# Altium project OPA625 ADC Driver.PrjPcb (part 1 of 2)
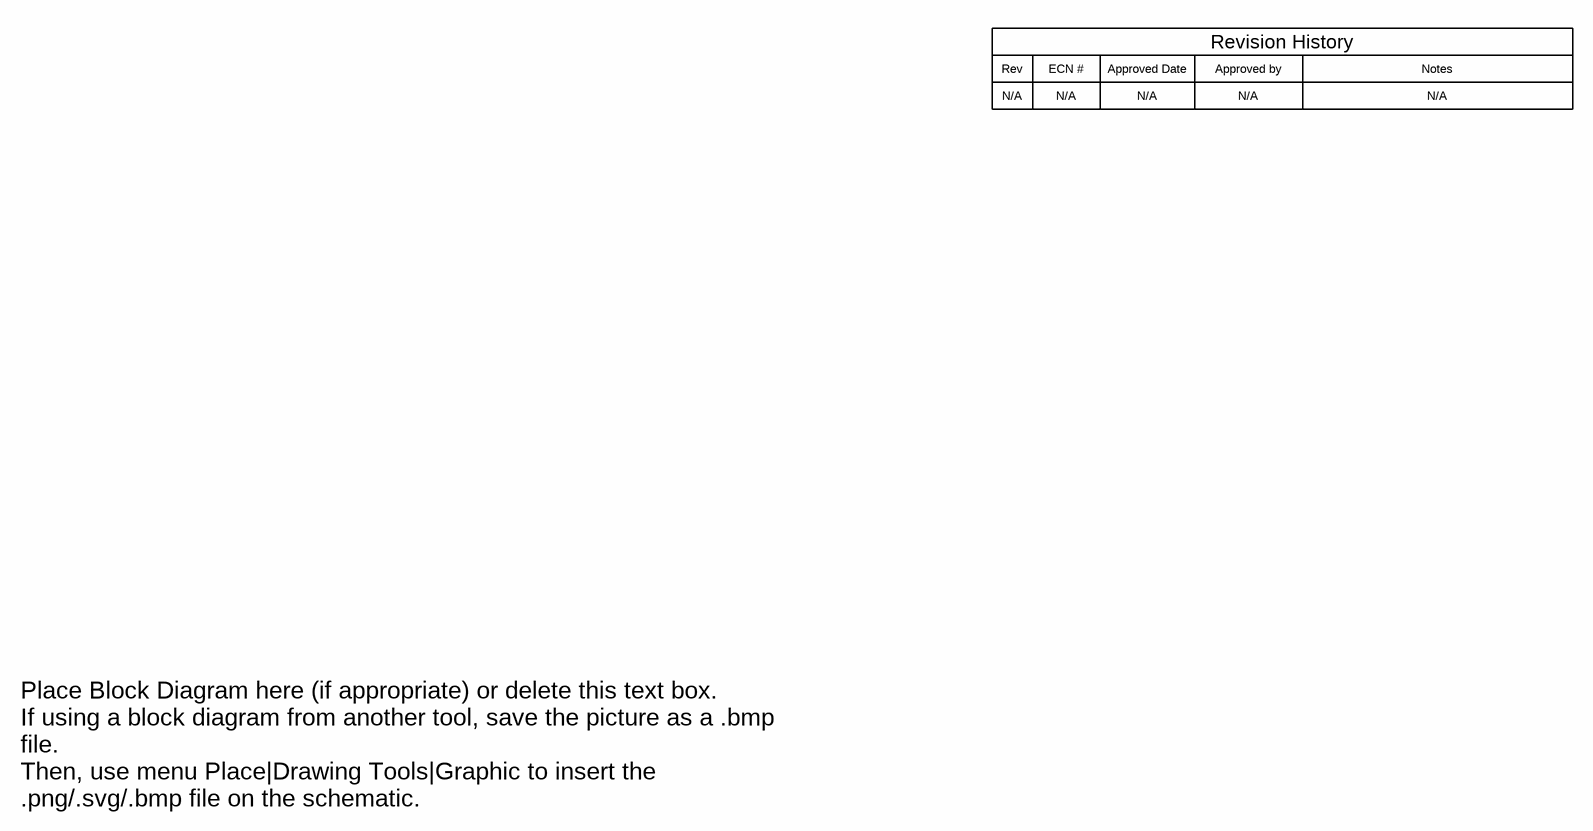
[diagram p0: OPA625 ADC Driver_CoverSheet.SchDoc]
CopyrightYear: 2016; EVM_Orderable: N/A; PCB_Rev: E1; PRJ_Customer: Public Release; PRJ_Engineer: Taras Dudar; PRJ_Number: TIDA-01050; PRJ_Title: OPA625 ADC Driver; SCH_Rev: E1; TechSupport: http://www.ti.com/support; TID: 01050
6 sheets, 429 parts. Net scope: global (net labels, ports and power ports of the same name join across sheets).
Board file: OPA625 ADC Driver.PcbDoc
Sheets:
  OPA625 ADC Driver_CoverSheet.SchDoc
  OPA625 ADC Driver_Power.SchDoc
  OPA625 ADC Driver_Connectors.SchDoc
  OPA625 ADC Driver_OPA625 ADC Driver.SchDoc
  OPA625 ADC Driver_Clock.SchDoc
  OPA625 ADC Driver_Hardware.SchDoc

## Sheet OPA625 ADC Driver_CoverSheet.SchDoc
size 431 x 279 mm; Date: Not shown in title block; ApprovedBy: Not shown in title block; CheckedBy: Not shown in title block; Author: Not shown in title block; CompanyName: Not shown in title block; Engineer: Not shown in title block; Organization: Not shown in title block; Address1: Not shown in title block; Address2: Not shown in title block; Address3: Not shown in title block; Address4: Not shown in title block; DocumentNumber: 1; Revision: Use project parameter SCH_Rev; SheetNumber: 1; SheetTotal: 8; PageSetup: Record=PageOptions¦CenterHorizontal=True¦CenterVertical=True¦PrintScale=1.00¦XCorrection=1.00¦YCorrection=1.00¦PrintKind=0¦BorderSize=5000000¦LeftOffset=0¦BottomOffset=0¦Orientation=2¦PaperLength=1000¦PaperWidth=1000¦Scale=100¦PaperSource=15¦PrintQuality=600¦MediaType=1¦DitherType=10¦PaperKind=Letter¦PrintScaleMode=1

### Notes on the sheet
- Rev
- N/A
- ECN #
- Approved Date
- Approved by
- Revision History
- Notes
- Place Block Diagram here (if appropriate) or delete this text box.
  If using a block diagram from another tool, save the picture as a .bmp file.
  Then, use menu Place|Drawing Tools|Graphic to insert the .png/.svg/.bmp file on the schematic.

## Sheet OPA625 ADC Driver_Power.SchDoc
size 558 x 431 mm; Date: Not shown in title block; ApprovedBy: Not shown in title block; CheckedBy: Not shown in title block; Author: Not shown in title block; CompanyName: Not shown in title block; Engineer: Not shown in title block; Organization: Not shown in title block; Address1: Not shown in title block; Address2: Not shown in title block; Address3: Not shown in title block; Address4: Not shown in title block; DocumentNumber: 2; Revision: Use project parameter SCH_Rev; SheetNumber: 2; SheetTotal: 8; PageSetup: Record=PageOptions¦CenterHorizontal=True¦CenterVertical=True¦PrintScale=1.00¦XCorrection=1.00¦YCorrection=1.00¦PrintKind=0¦BorderSize=5000000¦LeftOffset=0¦BottomOffset=0¦Orientation=2¦PaperLength=1000¦PaperWidth=1000¦Scale=100¦PaperSource=15¦PrintQuality=600¦MediaType=1¦DitherType=10¦PaperKind=Letter¦PrintScaleMode=1
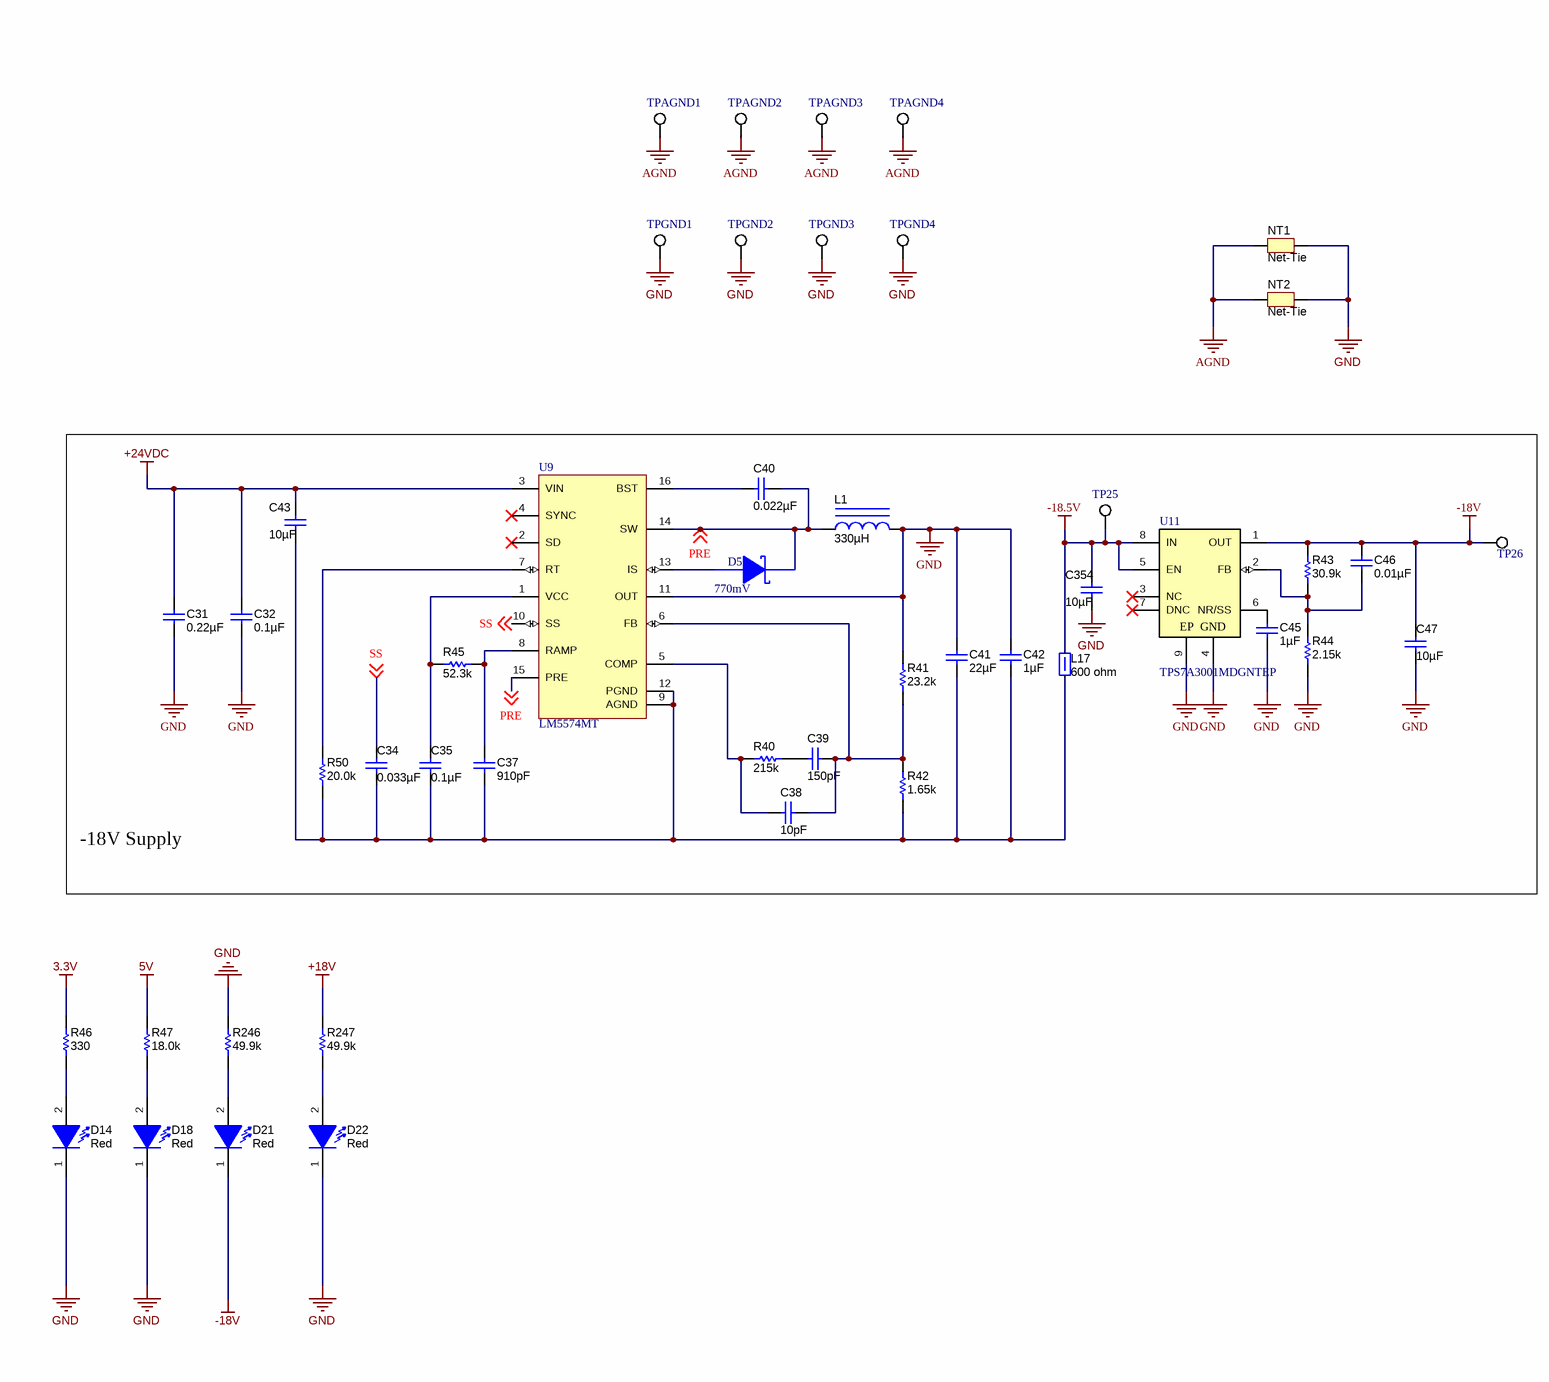
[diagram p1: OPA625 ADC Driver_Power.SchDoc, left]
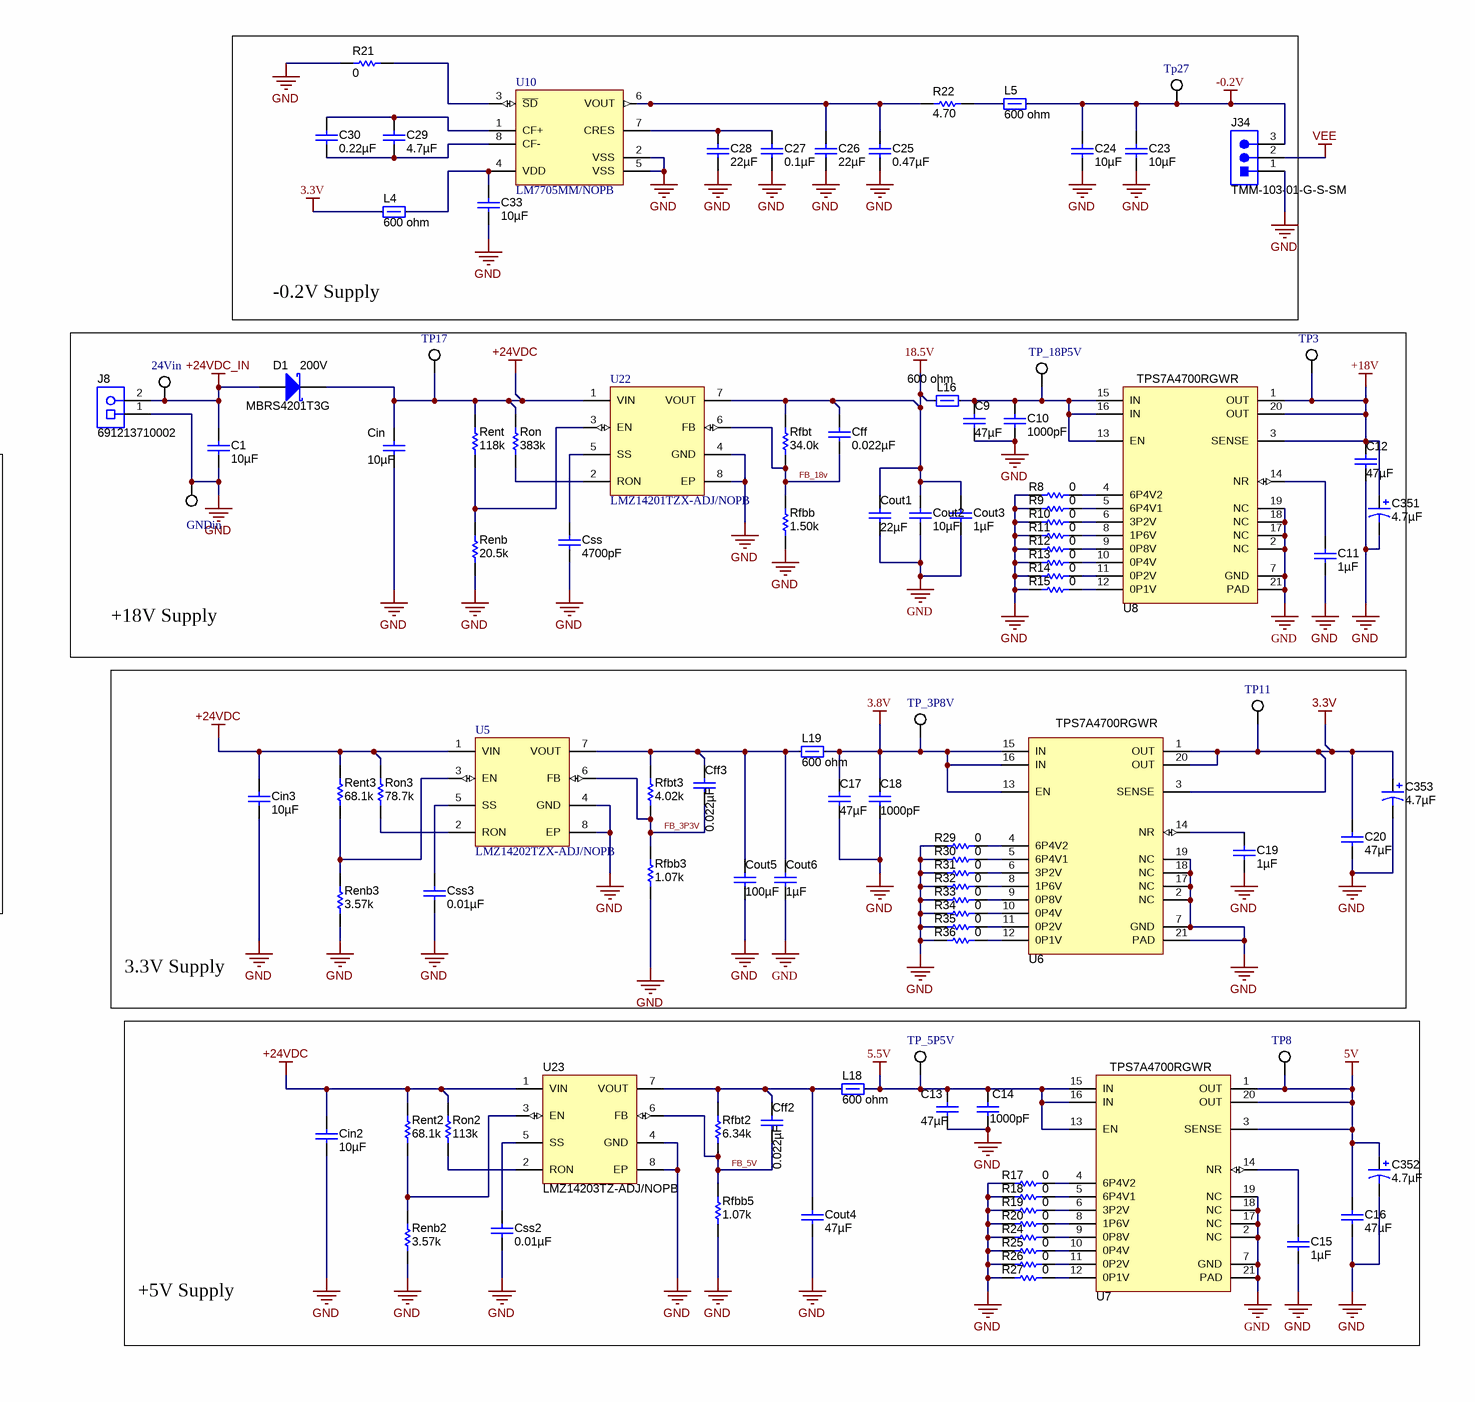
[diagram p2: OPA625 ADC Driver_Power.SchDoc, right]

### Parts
24Vin  5015  [Testpoint_Keystone_Miniature]  (value not drawn)
C1  ValueDisplayed: 10µF  [1210_280]  (hidden comment: UMK325AB7106KM-T)
C9  ValueDisplayed: 47µF  [1206_190]  (hidden comment: C3216X5R1E476M160AC)
C10  ValueDisplayed: 1000pF  [0603]  (hidden comment: CGA3E2X7R2A102K080AA)
C11  ValueDisplayed: 1µF  [0805_HV]  (hidden comment: C2012X7S2A105K125AB)
C12  ValueDisplayed: 47µF  [1206_190]  (hidden comment: C3216X5R1E476M160AC)
C13  ValueDisplayed: 47µF  [1206_190]  (hidden comment: C3216X5R1E476M160AC)
C14  ValueDisplayed: 1000pF  [0603]  (hidden comment: GRM1885C1H102FA01J)
C15  ValueDisplayed: 1µF  [0603]  (hidden comment: GRM188R71E105KA12D)
C16  ValueDisplayed: 47µF  [1206_190]  (hidden comment: C3216X5R1E476M160AC)
C17  ValueDisplayed: 47µF  [1206_190]  (hidden comment: C3216X5R1E476M160AC)
C18  ValueDisplayed: 1000pF  [0603]  (hidden comment: GRM1885C1H102FA01J)
C19  ValueDisplayed: 1µF  [0603]  (hidden comment: GRM188R71E105KA12D)
C20  ValueDisplayed: 47µF  [1206_190]  (hidden comment: C3216X5R1E476M160AC)
C23  ValueDisplayed: 10µF  [0603]  (hidden comment: GRM188R61A106ME69D)
C24  ValueDisplayed: 10µF  [0603]  (hidden comment: GRM188R61A106ME69D)
C25  ValueDisplayed: 0.47µF  [0603]  (hidden comment: GRM188R71E474KA12D)
C26  ValueDisplayed: 22µF  [0603]  (hidden comment: GRM188R60J226MEA0D)
C27  ValueDisplayed: 0.1µF  [0603]  (hidden comment: GRM188R61C104KA01D)
C28  ValueDisplayed: 22µF  [0603]  (hidden comment: GRM188R60J226MEA0D)
C29  ValueDisplayed: 4.7µF  [0603]  (hidden comment: GRM188R61A475MAAJ)
C30  ValueDisplayed: 0.22µF  [0603]  (hidden comment: GRM188R61A224KA01D)
C31  ValueDisplayed: 0.22µF  [0603]  (hidden comment: GCM188R71H224KA64D)
C32  ValueDisplayed: 0.1µF  [0603]  (hidden comment: C1608X7R1H104K080AA)
C33  ValueDisplayed: 10µF  [0603]  (hidden comment: GRM188R61A106ME69D)
C34  ValueDisplayed: 0.033µF  [0603]  (hidden comment: GRM188R71H333KA61D)
C35  ValueDisplayed: 0.1µF  [0603]  (hidden comment: C1608X7R1H104K080AA)
C37  ValueDisplayed: 910pF  [0603]  (hidden comment: C0603C911J5GACTU)
C38  ValueDisplayed: 10pF  [0603]  (hidden comment: CGA3E2C0G1H100D080AA)
C39  ValueDisplayed: 150pF  [0603]  (hidden comment: GRM1885C1H151JA01D)
C40  ValueDisplayed: 0.022µF  [0603]  (hidden comment: GRM188R71H223KA01D)
C41  ValueDisplayed: 22µF  [0805_HV]  (hidden comment: C2012X5R1V226M125AC)
C42  ValueDisplayed: 1µF  [0805_HV]  (hidden comment: C2012X7S2A105K125AB)
C43  ValueDisplayed: 10µF  [1210_280]  (hidden comment: UMK325AB7106KM-T)
C45  ValueDisplayed: 1µF  [0805_HV]  (hidden comment: C2012X7S2A105K125AB)
C46  ValueDisplayed: 0.01µF  [0603]  (hidden comment: GCM188R71H103KA37D)
C47  ValueDisplayed: 10µF  [1210_280]  (hidden comment: UMK325AB7106KM-T)
C351  ValueDisplayed: 4.7µF  [6032-28]  (hidden comment: 293D475X9025C2TE3)
C352  ValueDisplayed: 4.7µF  [6032-28]  (hidden comment: 293D475X9025C2TE3)
C353  ValueDisplayed: 4.7µF  [6032-28]  (hidden comment: 293D475X9025C2TE3)
C354  ValueDisplayed: 10µF  [1210_280]  (hidden comment: UMK325AB7106KM-T)
Cff  ValueDisplayed: 0.022µF  [0603]  (hidden comment: C1608X7R2A223K080AA)
Cff2  ValueDisplayed: 0.022µF  [0805_HV]  (hidden comment: 08055C223KAT2A)
Cff3  ValueDisplayed: 0.022µF  [0805_HV]  (hidden comment: 08055C223KAT2A)
Cin  ValueDisplayed: 10µF  [1210_280]  (hidden comment: UMK325AB7106KM-T)
Cin2  ValueDisplayed: 10µF  [1210_280]  (hidden comment: UMK325AB7106KM-T)
Cin3  ValueDisplayed: 10µF  [1210_280]  (hidden comment: UMK325AB7106KM-T)
Cout1  ValueDisplayed: 22µF  [0805_HV]  (hidden comment: C2012JB1V226M125AC)
Cout2  ValueDisplayed: 10µF  [1210_280]  (hidden comment: UMK325AB7106KM-T)
Cout3  ValueDisplayed: 1µF  [0805_HV]  (hidden comment: C2012X7S2A105K125AB)
Cout4  ValueDisplayed: 47µF  [1206_190]  (hidden comment: C3216X5R1E476M160AC)
Cout5  ValueDisplayed: 100µF  [1210_280]  (hidden comment: C3225X6S0J107M250AC)
Cout6  ValueDisplayed: 1µF  [0603]  (hidden comment: C0603C105K3RACTU)
Css  ValueDisplayed: 4700pF  [0603]  (hidden comment: CGA3E2X7R2A472K080AA)
Css2  ValueDisplayed: 0.01µF  [0603]  (hidden comment: GRM188R70J103KA01D)
Css3  ValueDisplayed: 0.01µF  [0603]  (hidden comment: GRM188R70J103KA01D)
D1  value 200V  [SMC]  (hidden comment: MBRS4201T3G)
D5  value 770mV  (hidden comment: DFLS1100-7)
D14  value Red  [WL-SMCW_RED]  (hidden comment: 150060RS75000)
D18  value Red  [WL-SMCW_RED]  (hidden comment: 150060RS75000)
D21  value Red  [WL-SMCW_RED]  (hidden comment: 150060RS75000)
D22  value Red  [WL-SMCW_RED]  (hidden comment: 150060RS75000)
GNDin  5015  [Testpoint_Keystone_Miniature]  (value not drawn)
J8  691213710002  [Wurth_691213710002]
J34  TMM-103-01-G-S-SM  [Samtec_TMM-103-01-x-S-SM]
L1  ValueDisplayed: 330µH  [DR73]  (hidden comment: DR73-331-R)
L4  value 600 ohm  [0805_HV]  (hidden comment: MPZ2012S601A)
L5  value 600 ohm  [0805_HV]  (hidden comment: MPZ2012S601A)
L16  value 600 ohm  [0805_HV]  (hidden comment: MPZ2012S601A)
L17  value 600 ohm  [0805_HV]  (hidden comment: MPZ2012S601A)
L18  value 600 ohm  [0805_HV]  (hidden comment: MPZ2012S601A)
L19  value 600 ohm  [0805_HV]  (hidden comment: MPZ2012S601A)
NT1  Net-Tie  [Net-Tie_50milWide_30milLong]  (net tie, no BOM)
NT2  Net-Tie  [Net-Tie_50milWide_30milLong]  (net tie, no BOM)
R8  ValueDisplayed: 0  [0402]  (hidden comment: ERJ-2GE0R00X)
R9  ValueDisplayed: 0  [0402]  (hidden comment: ERJ-2GE0R00X)
R10  ValueDisplayed: 0  [0402]  (hidden comment: ERJ-2GE0R00X)
R11  ValueDisplayed: 0  [0402]  (hidden comment: ERJ-2GE0R00X)
R12  ValueDisplayed: 0  [0402]  (hidden comment: ERJ-2GE0R00X)
R13  ValueDisplayed: 0  [0402]  (hidden comment: ERJ-2GE0R00X)
R14  ValueDisplayed: 0  [0402]  (hidden comment: ERJ-2GE0R00X)
R15  ValueDisplayed: 0  [0402]  (hidden comment: ERJ-2GE0R00X)
R17  ValueDisplayed: 0  [0402]  (hidden comment: ERJ-2GE0R00X)
R18  ValueDisplayed: 0  [0402]  (hidden comment: ERJ-2GE0R00X)
R19  ValueDisplayed: 0  [0402]  (hidden comment: ERJ-2GE0R00X)
R20  ValueDisplayed: 0  [0402]  (hidden comment: ERJ-2GE0R00X)
R21  ValueDisplayed: 0  [0603]  (hidden comment: CRCW06030000Z0EA)
R22  ValueDisplayed: 4.70  [0603]  (hidden comment: RT0603DRE074R7L)
R24  ValueDisplayed: 0  [0402]  (hidden comment: ERJ-2GE0R00X)
R25  ValueDisplayed: 0  [0402]  (hidden comment: ERJ-2GE0R00X)
R26  ValueDisplayed: 0  [0402]  (hidden comment: ERJ-2GE0R00X)
R27  ValueDisplayed: 0  [0402]  (hidden comment: ERJ-2GE0R00X)
R29  ValueDisplayed: 0  [0402]  (hidden comment: ERJ-2GE0R00X)
R30  ValueDisplayed: 0  [0402]  (hidden comment: ERJ-2GE0R00X)
R31  ValueDisplayed: 0  [0402]  (hidden comment: ERJ-2GE0R00X)
R32  ValueDisplayed: 0  [0402]  (hidden comment: ERJ-2GE0R00X)
R33  ValueDisplayed: 0  [0402]  (hidden comment: ERJ-2GE0R00X)
R34  ValueDisplayed: 0  [0402]  (hidden comment: ERJ-2GE0R00X)
R35  ValueDisplayed: 0  [0402]  (hidden comment: ERJ-2GE0R00X)
R36  ValueDisplayed: 0  [0402]  (hidden comment: ERJ-2GE0R00X)
R40  ValueDisplayed: 215k  [0603]  (hidden comment: RT0603BRD07215KL)
R41  ValueDisplayed: 23.2k  [0603]  (hidden comment: RG1608P-2322-B-T5)
R42  ValueDisplayed: 1.65k  [0603]  (hidden comment: RG1608P-1651-B-T5)
R43  ValueDisplayed: 30.9k  [0603]  (hidden comment: RG1608P-3092-B-T5)
R44  ValueDisplayed: 2.15k  [0603]  (hidden comment: RT0603BRD072K15L)
R45  ValueDisplayed: 52.3k  [0603]  (hidden comment: RT0603BRD0752K3L)
R46  ValueDisplayed: 330  [0603]  (hidden comment: RC0603JR-07330RL)
R47  ValueDisplayed: 18.0k  [0603]  (hidden comment: RT0603BRD0718KL)
R50  ValueDisplayed: 20.0k  [0603]  (hidden comment: RG1608P-203-B-T5)
R246  ValueDisplayed: 49.9k  [0603]  (hidden comment: RG1608P-4992-B-T5)
R247  ValueDisplayed: 49.9k  [0603]  (hidden comment: RG1608P-4992-B-T5)
Renb  ValueDisplayed: 20.5k  [0805_HV]  (hidden comment: CRCW080520K5FKEA)
Renb2  ValueDisplayed: 3.57k  [0603]  (hidden comment: RG1608P-3571-B-T5)
Renb3  ValueDisplayed: 3.57k  [0603]  (hidden comment: RG1608P-3571-B-T5)
Rent  value 118k  [0805_HV]  (hidden comment: RT0805BRD07118KL)
Rent2  ValueDisplayed: 68.1k  [0603]  (hidden comment: RT0603BRD0768K1L)
Rent3  ValueDisplayed: 68.1k  [0603]  (hidden comment: RT0603BRD0768K1L)
Rfbb  ValueDisplayed: 1.50k  [0603]  (hidden comment: RG1608P-152-B-T5)
Rfbb3  ValueDisplayed: 1.07k  [0805_HV]  (hidden comment: RT0805BRD071K07L)
Rfbb5  ValueDisplayed: 1.07k  [0805_HV]  (hidden comment: RT0805BRD071K07L)
Rfbt  ValueDisplayed: 34.0k  [0603]  (hidden comment: RT0603BRD0734KL)
Rfbt2  ValueDisplayed: 6.34k  [0603]  (hidden comment: CPF0603B6K34E)
Rfbt3  ValueDisplayed: 4.02k  [0603]  (hidden comment: RG1608P-4021-B-T5)
Ron  ValueDisplayed: 383k  [0603]  (hidden comment: RT0603BRD07383KL)
Ron2  ValueDisplayed: 113k  [0603]  (hidden comment: RT0603BRD07113KL)
Ron3  ValueDisplayed: 78.7k  [0603]  (hidden comment: RT0603BRD0778K7L)
TP3  5015  [Testpoint_Keystone_Miniature]  (value not drawn)
TP8  5015  [Testpoint_Keystone_Miniature]  (value not drawn)
TP11  5015  [Testpoint_Keystone_Miniature]  (value not drawn)
TP17  5015  [Testpoint_Keystone_Miniature]  (value not drawn)
TP25  5015  [Testpoint_Keystone_Miniature]  (value not drawn)
TP26  5015  [Testpoint_Keystone_Miniature]  (value not drawn)
Tp27  5015  [Testpoint_Keystone_Miniature]  (value not drawn)
TP_3P8V  5015  [Testpoint_Keystone_Miniature]  (value not drawn)
TP_5P5V  5015  [Testpoint_Keystone_Miniature]  (value not drawn)
TP_18P5V  5015  [Testpoint_Keystone_Miniature]  (value not drawn)
TPAGND1  5015  [Testpoint_Keystone_Miniature]  (value not drawn)
TPAGND2  5015  [Testpoint_Keystone_Miniature]  (value not drawn)
TPAGND3  5015  [Testpoint_Keystone_Miniature]  (value not drawn)
TPAGND4  5015  [Testpoint_Keystone_Miniature]  (value not drawn)
TPGND1  5015  [Testpoint_Keystone_Miniature]  (value not drawn)
TPGND2  5015  [Testpoint_Keystone_Miniature]  (value not drawn)
TPGND3  5015  [Testpoint_Keystone_Miniature]  (value not drawn)
TPGND4  5015  [Testpoint_Keystone_Miniature]  (value not drawn)
U5  LMZ14202TZX-ADJ/NOPB  [TZA07A_V]
U6  TPS7A4700RGWR  [RGW0020A]
U7  TPS7A4700RGWR  [RGW0020A]
U8  TPS7A4700RGWR  [RGW0020A]
U9  LM5574MT  [MTC16_N]
U10  LM7705MM/NOPB  [MUA08A_N]
U11  TPS7A3001MDGNTEP  [DGN0008D_N]
U22  LMZ14201TZX-ADJ/NOPB  [TZA07A_V]
U23  LMZ14203TZ-ADJ/NOPB  [TZA07A_V]

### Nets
3.3V: C20.1 C353.1(+) L4.2 R46.2 TP11.1 U6.1(OUT) U6.3(SENSE) U6.20(OUT)
3.8V: C17.1 C18.1 L19.2 TP_3P8V.1 U6.13(EN) U6.15(IN) U6.16(IN)
5.5V: C13.1 C14.1 L18.2 TP_5P5V.1 U7.13(EN) U7.15(IN) U7.16(IN)
5V: C16.1 C352.1(+) R47.2 TP8.1 U7.1(OUT) U7.3(SENSE) U7.20(OUT)
18.5V: Cff.1 Cout1.1 Cout2.1 Cout3.1 L16.2 Rfbt.2 U22.7(VOUT)
+18V: C12.1 C351.1(+) R247.2 TP3.1 U8.1(OUT) U8.3(SENSE) U8.20(OUT)
+24VDC: C31.1 C32.1 C43.1 Cin.1 Cin2.1 Cin3.1 D1.1(K) Rent.2 Rent2.2 Rent3.2 Ron.2 Ron2.2 Ron3.2 TP17.1 U5.1(VIN) U9.3(VIN) U22.1(VIN) U23.1(VIN)
+24VDC_IN: 24Vin.1 C1.1 D1.2(A) J8.2
-0.2V: C23.1 C24.1 J34.3 L5.1 Tp27.1
-18.5V: C354.1 L17.1 TP25.1 U11.5(EN) U11.8(IN)
-18V: C46.1 C47.1 D21.1(K) R43.2 TP26.1 U11.1(OUT)
AGND: NT1.1 NT2.1 TPAGND1.1 TPAGND2.1 TPAGND3.1 TPAGND4.1
GND: C1.2 C9.2 C10.2 C11.2 C12.2 C13.2 C14.2 C15.1 C16.2 C17.2 C18.2 C19.1 C20.2 C23.2 C24.2 C25.2 C26.2 C27.2 C28.2 C31.2 C32.2 C33.2 C41.1 C42.1 C45.2 C47.2 C351.2(-) C352.2(-) C353.2(-) C354.2 Cin.2 Cin2.2 Cin3.2 Cout1.2 Cout2.2 Cout3.2 Cout4.2 Cout5.2 Cout6.2 Css.1 Css2.2 Css3.2 D14.1(K) D18.1(K) D22.1(K) GNDin.1 J8.1 J34.1 L1.2 NT1.2 NT2.2 R8.1 R9.1 R10.1 R11.1 R12.1 R13.1 R14.1 R15.1 R17.1 R18.1 R19.1 R20.1 R21.1 R24.1 R25.1 R26.1 R27.1 R29.1 R30.1 R31.1 R32.1 R33.1 R34.1 R35.1 R36.1 R41.2 R44.1 R246.2 Renb.1 Renb2.1 Renb3.1 Rfbb.1 Rfbb3.1 Rfbb5.1 TPGND1.1 TPGND2.1 TPGND3.1 TPGND4.1 U5.4(GND) U5.8(EP) U6.2(NC) U6.7(GND) U6.17(NC) U6.18(NC) U6.19(NC) U6.21(PAD) U7.2(NC) U7.7(GND) U7.17(NC) U7.18(NC) U7.19(NC) U7.21(PAD) U8.2(NC) U8.7(GND) U8.17(NC) U8.18(NC) U8.19(NC) U8.21(PAD) U9.11(OUT) U10.2(VSS) U10.5(VSS) U11.4(GND) U11.9(EP) U22.4(GND) U22.8(EP) U23.4(GND) U23.8(EP)
VEE: J34.2
FB_3P3V: Cff3.2 Rfbb3.2 Rfbt3.1 U5.6(FB)
FB_5V: Cff2.2 Rfbb5.2 Rfbt2.1 U23.6(FB)
FB_18v: Cff.2 Rfbb.2 Rfbt.1 U22.6(FB)
PRE: C40.1 D5.1(K) L1.1 U9.14(SW) U9.15(PRE) ; off-sheet PRE
SS: C34.1 U9.10(SS) ; off-sheet SS
NetC9_1: C9.1 C10.1 L16.1 TP_18P5V.1 U8.13(EN) U8.15(IN) U8.16(IN)
NetC11_1: C11.1 U8.14(NR)
NetC15_2: C15.2 U7.14(NR)
NetC19_2: C19.2 U6.14(NR)
NetC25_1: C25.1 C26.1 R22.1 U10.6(VOUT)
NetC27_1: C27.1 C28.1 U10.7(CRES)
NetC29_1: C29.1 C30.1 U10.1(CF+)
NetC29_2: C29.2 C30.2 U10.8(CF-)
NetC33_1: C33.1 L4.1 U10.4(VDD)
NetC34_2: C34.2 C35.2 C37.2 C41.2 C42.2 C43.2 L17.2 R42.1 R50.1 U9.9(AGND) U9.12(PGND)
NetC35_1: C35.1 R45.1 U9.1(VCC)
NetC37_1: C37.1 R45.2 U9.8(RAMP)
NetC38_1: C38.1 C39.1 R41.1 R42.2 U9.6(FB)
NetC38_2: C38.2 R40.1 U9.5(COMP)
NetC39_2: C39.2 R40.2
NetC40_2: C40.2 U9.16(BST)
NetC45_1: C45.1 U11.6(NR/SS)
NetC46_2: C46.2 R43.1 R44.2 U11.2(FB)
NetCff2_1: Cff2.1 Cout4.1 L18.1 Rfbt2.2 U23.7(VOUT)
NetCff3_1: Cff3.1 Cout5.1 Cout6.1 L19.1 Rfbt3.2 U5.7(VOUT)
NetCss2_1: Css2.1 U23.5(SS)
NetCss3_1: Css3.1 U5.5(SS)
NetCss_2: Css.2 U22.5(SS)
NetD5_2: D5.2(A) U9.13(IS)
NetD14_2: D14.2(A) R46.1
NetD18_2: D18.2(A) R47.1
NetD21_2: D21.2(A) R246.1
NetD22_2: D22.2(A) R247.1
NetL5_2: L5.2 R22.2
NetR8_2: R8.2 U8.4(6P4V2)
NetR9_2: R9.2 U8.5(6P4V1)
NetR10_2: R10.2 U8.6(3P2V)
NetR11_2: R11.2 U8.8(1P6V)
NetR12_2: R12.2 U8.9(0P8V)
NetR13_2: R13.2 U8.10(0P4V)
NetR14_2: R14.2 U8.11(0P2V)
NetR15_2: R15.2 U8.12(0P1V)
NetR17_2: R17.2 U7.4(6P4V2)
NetR18_2: R18.2 U7.5(6P4V1)
NetR19_2: R19.2 U7.6(3P2V)
NetR20_2: R20.2 U7.8(1P6V)
NetR21_2: R21.2 U10.3(~{SD})
NetR24_2: R24.2 U7.9(0P8V)
NetR25_2: R25.2 U7.10(0P4V)
NetR26_2: R26.2 U7.11(0P2V)
NetR27_2: R27.2 U7.12(0P1V)
NetR29_2: R29.2 U6.4(6P4V2)
NetR30_2: R30.2 U6.5(6P4V1)
NetR31_2: R31.2 U6.6(3P2V)
NetR32_2: R32.2 U6.8(1P6V)
NetR33_2: R33.2 U6.9(0P8V)
NetR34_2: R34.2 U6.10(0P4V)
NetR35_2: R35.2 U6.11(0P2V)
NetR36_2: R36.2 U6.12(0P1V)
NetR50_2: R50.2 U9.7(RT)
NetRenb2_2: Renb2.2 Rent2.1 U23.3(EN)
NetRenb3_2: Renb3.2 Rent3.1 U5.3(EN)
NetRenb_2: Renb.2 Rent.1 U22.3(EN)
NetRon2_1: Ron2.1 U23.2(RON)
NetRon3_1: Ron3.1 U5.2(RON)
NetRon_1: Ron.1 U22.2(RON)

Not connected (* = marked no-connect by the designer): U9 2(SD)* 4(SYNC)*; U11 3(NC)* 7(DNC)*

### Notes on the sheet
- -0.2V Supply
- +18V Supply
- -18V Supply
- 3.3V Supply
- +5V Supply

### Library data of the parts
24Vin GNDin TP3 TP8 TP11 TP17 TP25 TP26 Tp27 TP_3P8V TP_5P5V TP_18P5V TPAGND1-TPAGND4 TPGND1-TPGND4 = 5015: Test Point, Miniature, SMT; Manufacturer: Keystone; CompType: Test Point Loop
C1 Cin2 Cin3 Cout2 = UMK325AB7106KM-T: CAP, CERM, 10 µF, 50 V, +/- 10%, X7R, 1210; Manufacturer: Taiyo Yuden; Polarized: N; CompType: Capacitor; Value: 10uF; U/M: EA; Cap_F: 0.00001; Tolerance_%: 10; Value1: Unknown; VDC_V: 50; Value2: 50V; TaMin_C: -55; TaMax_C: 125; Cap_Case: 1210; SizeArea_mm2: 8; SizeAreaWB_mm2: 14.7; SizeX_mm: 3.2; SizeY_mm: 2.5; SizeZ_mm: 2.8; AEC Category: Q200
C9 C12 C13 C16 C17 C20 Cout4 = C3216X5R1E476M160AC: CAP, CERM, 47 µF, 25 V, +/- 20%, X5R, 1206_190; Manufacturer: TDK; Polarized: N; CompType: Capacitor; Value: 47uF; U/M: EA; Cap_F: 0.000047; Tolerance_%: 20; Value1: Unknown; VDC_V: 25; Value2: 25V; TaMin_C: -55; TaMax_C: 85; Cap_Case: 1206; AEC Category: Q200
C10 = CGA3E2X7R2A102K080AA: CAP, CERM, 1000 pF, 100 V, +/- 10%, X7R, AEC-Q200 Grade 1, 0603; Manufacturer: TDK; Polarized: N; CompType: Capacitor; Value: 1000pF; U/M: EA; Cap_F: 0.000000001; Tolerance_%: 10; ESR_ohm: 1.97137; Value1: 1.97137 ohm; VDC_V: 100; Value2: 100V; IRMS_A: 0.305705; TaMin_C: -55; TaMax_C: 125; SizeArea_mm2: 1.28; SizeAreaWB_mm2: 4.68; SizeX_mm: 1.6; SizeY_mm: 0.8; SizeZ_mm: 1; AEC Category: Q200; AEC Qualified: Y
C11 C42 C45 Cout3 = C2012X7S2A105K125AB: CAP, CERM, 1 µF, 100 V, +/- 10%, X7S, 0805; Manufacturer: TDK; Polarized: N; CompType: Capacitor; Value: 1uF; U/M: EA; Cap_F: 0.000001; Tolerance_%: 10; ESR_ohm: 0.008255; Value1: 0.008255 ohm; VDC_V: 100; Value2: 100V; IRMS_A: 2.27442; TaMin_C: -55; TaMax_C: 125; Cap_Case: 0805; SizeArea_mm2: 2.5; SizeAreaWB_mm2: 6.75; SizeX_mm: 2; SizeY_mm: 1.25; SizeZ_mm: 1.45; AEC Category: Q200
C14 C18 = GRM1885C1H102FA01J: CAP, CERM, 1000 pF, 50 V, +/- 1%, C0G/NP0, 0603; Manufacturer: MuRata; Polarized: N; CompType: Capacitor; Value: 1000pF; U/M: EA; Cap_F: 0.000000001; Tolerance_%: 1; Value1: Unknown; VDC_V: 50; Value2: 50V; TaMin_C: -55; TaMax_C: 125; AEC Category: Q200
C15 C19 = GRM188R71E105KA12D: CAP, CERM, 1 µF, 25 V, +/- 10%, X7R, 0603; Manufacturer: MuRata; Polarized: N; CompType: Capacitor; Value: 1uF; U/M: EA; Cap_F: 0.000001; Tolerance_%: 10; Value1: Unknown; VDC_V: 25; Value2: 25V; TaMin_C: -55; TaMax_C: 125; AEC Category: Q200
C23 C24 C33 = GRM188R61A106ME69D: CAP, CERM, 10 µF, 10 V, +/- 20%, X5R, 0603; Manufacturer: MuRata; Polarized: N; CompType: Capacitor; Value: 10uF; U/M: EA; Cap_F: 0.00001; Tolerance_%: 20; Value1: Unknown; VDC_V: 10; Value2: 10V; TaMin_C: -55; TaMax_C: 85; SizeArea_mm2: 1.28; SizeAreaWB_mm2: 4.68; SizeX_mm: 1.6; SizeY_mm: 0.8; SizeZ_mm: 1; AEC Category: Q200
C25 = GRM188R71E474KA12D: CAP, CERM, 0.47 µF, 25 V, +/- 10%, X7R, 0603; Manufacturer: MuRata; Polarized: N; CompType: Capacitor; Value: 0.47uF; U/M: EA; Cap_F: 0.00000047; Tolerance_%: 10; Value1: Unknown; VDC_V: 25; Value2: 25V; TaMin_C: -55; TaMax_C: 125; SizeArea_mm2: 1.28; SizeAreaWB_mm2: 4.68; SizeX_mm: 1.6; SizeY_mm: 0.8; SizeZ_mm: 1; AEC Category: Q200
C26 C28 = GRM188R60J226MEA0D: CAP, CERM, 22 µF, 6.3 V, +/- 20%, X5R, 0603; Manufacturer: MuRata; Polarized: N; CompType: Capacitor; Value: 22uF; U/M: EA; Cap_F: 0.000022; Tolerance_%: 20; Value1: Unknown; VDC_V: 6.3; Value2: 6.3V; TaMin_C: -55; TaMax_C: 85; SizeArea_mm2: 1.28; SizeAreaWB_mm2: 4.68; SizeX_mm: 1.6; SizeY_mm: 0.8; SizeZ_mm: 1; AEC Category: Q200
C27 = GRM188R61C104KA01D: CAP, CERM, 0.1 µF, 16 V, +/- 10%, X5R, 0603; Manufacturer: MuRata; Polarized: N; CompType: Capacitor; Value: 0.1uF; U/M: EA; Cap_F: 0.0000001; Tolerance_%: 10; Value1: Unknown; VDC_V: 16; Value2: 16V; TaMin_C: -55; TaMax_C: 85; SizeArea_mm2: 1.28; SizeAreaWB_mm2: 4.68; SizeX_mm: 1.6; SizeY_mm: 0.8; SizeZ_mm: 1; AEC Category: Q200
C29 = GRM188R61A475MAAJ: CAP, CERM, 4.7 µF, 10 V, +/- 20%, X5R, 0603; Manufacturer: MuRata; Polarized: N; CompType: Capacitor; Value: 4.7uF; U/M: EA; Cap_F: 0.0000047; Tolerance_%: 20; Value1: Unknown; VDC_V: 10; Value2: 10V; TaMin_C: -55; TaMax_C: 85; SizeArea_mm2: 1.28; SizeAreaWB_mm2: 4.68; SizeX_mm: 1.6; SizeY_mm: 0.8; SizeZ_mm: 1; AEC Category: Q200
C30 = GRM188R61A224KA01D: CAP, CERM, 0.22 µF, 10 V, +/- 10%, X5R, 0603; Manufacturer: MuRata; Polarized: N; CompType: Capacitor; Value: 0.22uF; U/M: EA; Cap_F: 0.00000022; Tolerance_%: 10; Value1: Unknown; Value2: 10V; TaMin_C: -55; TaMax_C: 85; SizeArea_mm2: 1.28; SizeAreaWB_mm2: 4.68; SizeX_mm: 1.6; SizeY_mm: 0.8; SizeZ_mm: 1; AEC Category: Q200
C31 = GCM188R71H224KA64D: CAP, CERM, 0.22 µF, 50 V, +/- 10%, X7R, AEC-Q200 Grade 1, 0603; Manufacturer: MuRata; Polarized: N; CompType: Capacitor; Value: 0.22uF; U/M: EA; Cap_F: 0.00000022; Tolerance_%: 10; Value1: Unknown; VDC_V: 50; Value2: 50V; TaMin_C: -55; TaMax_C: 125; SizeArea_mm2: 1.28; SizeAreaWB_mm2: 4.68; SizeX_mm: 1.6; SizeY_mm: 0.8; SizeZ_mm: 1; AEC Category: Q200; AEC Qualified: Y
C32 C35 = C1608X7R1H104K080AA: CAP, CERM, 0.1 µF, 50 V, +/- 10%, X7R, 0603; Manufacturer: TDK; Polarized: N; CompType: Capacitor; Value: 0.1uF; U/M: EA; Cap_F: 0.0000001; Tolerance_%: 10; ESR_ohm: 0.0296; Value1: 0.0296 ohm; VDC_V: 50; Value2: 50V; IRMS_A: 0.97199; TaMin_C: -55; TaMax_C: 125; SizeArea_mm2: 1.28; SizeAreaWB_mm2: 4.68; SizeX_mm: 1.6; SizeY_mm: 0.8; SizeZ_mm: 1; AEC Category: Q200
C34 = GRM188R71H333KA61D: CAP, CERM, 0.033 µF, 50 V, +/- 10%, X7R, 0603; Manufacturer: MuRata; Polarized: N; CompType: Capacitor; Value: 0.033uF; U/M: EA; Cap_F: 0.000000033; Tolerance_%: 10; Value1: Unknown; VDC_V: 50; Value2: 50V; TaMin_C: -55; TaMax_C: 125; SizeArea_mm2: 1.28; SizeAreaWB_mm2: 4.68; SizeX_mm: 1.6; SizeY_mm: 0.8; SizeZ_mm: 1; AEC Category: Q200
C37 = C0603C911J5GACTU: CAP, CERM, 910 pF, 50 V, +/- 5%, C0G/NP0, 0603; Manufacturer: Kemet; Polarized: N; CompType: Capacitor; Value: 910pF; U/M: EA; Cap_F: 0.00000000091; Tolerance_%: 5; Value1: Unknown; VDC_V: 50; Value2: 50V; TaMin_C: -55; TaMax_C: 125; SizeArea_mm2: 1.28; SizeAreaWB_mm2: 4.68; SizeX_mm: 1.6; SizeY_mm: 0.8; SizeZ_mm: 1; AEC Category: Q200
C38 = CGA3E2C0G1H100D080AA: CAP, CERM, 10 pF, 50 V, +/- 5%, C0G/NP0, AEC-Q200 Grade 1, 0603; Manufacturer: TDK; Polarized: N; CompType: Capacitor; Value: 10pF; U/M: EA; Cap_F: 0.00000000001; Tolerance_%: 5; Value1: Unknown; VDC_V: 50; Value2: 50V; TaMin_C: -55; TaMax_C: 125; SizeArea_mm2: 1.28; SizeAreaWB_mm2: 4.68; SizeX_mm: 1.6; SizeY_mm: 0.8; SizeZ_mm: 1; AEC Category: Q200; AEC Qualified: Y
C39 = GRM1885C1H151JA01D: CAP, CERM, 150 pF, 50 V, +/- 5%, C0G/NP0, 0603; Manufacturer: MuRata; Polarized: N; CompType: Capacitor; Value: 150pF; U/M: EA; Cap_F: 0.00000000015; Tolerance_%: 5; Value1: Unknown; VDC_V: 50; Value2: 50V; TaMin_C: -55; TaMax_C: 125; SizeArea_mm2: 1.28; SizeAreaWB_mm2: 4.68; SizeX_mm: 1.6; SizeY_mm: 0.8; SizeZ_mm: 1; AEC Category: Q200
C40 = GRM188R71H223KA01D: CAP, CERM, 0.022 µF, 50 V, +/- 10%, X7R, 0603; Manufacturer: MuRata; Polarized: N; CompType: Capacitor; Value: 0.022uF; U/M: EA; Cap_F: 0.000000022; Tolerance_%: 10; Value1: Unknown; VDC_V: 50; Value2: 50V; TaMin_C: -55; TaMax_C: 125; SizeArea_mm2: 1.28; SizeAreaWB_mm2: 4.68; SizeX_mm: 1.6; SizeY_mm: 0.8; SizeZ_mm: 1; AEC Category: Q200
C41 = C2012X5R1V226M125AC: CAP, CERM, 22 µF, 35 V, +/- 20%, X5R, 0805; Manufacturer: TDK; Polarized: N; CompType: Capacitor; Value: 22uF; U/M: EA; Cap_F: 0.000022; Tolerance_%: 20; ESR_ohm: 0.00205; Value1: 0.00205 ohm; VDC_V: 35; Value2: 35V; IRMS_A: 4.55587; TaMin_C: -55; TaMax_C: 85; Cap_Case: 0805; SizeArea_mm2: 2.5; SizeAreaWB_mm2: 6.75; SizeX_mm: 2; SizeY_mm: 1.25; SizeZ_mm: 1.45; AEC Category: Q200
C43 C47 C354 Cin = UMK325AB7106KM-T: CAP, CERM, 10 µF, 50 V, +/- 10%, X7R, 1210; Manufacturer: Taiyo Yuden; Polarized: N; CompType: Capacitor; Value: 10uF; U/M: EA; Cap_F: 0.00001; Tolerance_%: 10; Value1: Unknown; VDC_V: 50; Value2: 50V; TaMin_C: -55; TaMax_C: 125; Cap_Case: 1210; AEC Category: Q200
C46 = GCM188R71H103KA37D: CAP, CERM, 0.01 µF, 50 V, +/- 10%, X7R, AEC-Q200 Grade 1, 0603; Manufacturer: MuRata; Polarized: N; CompType: Capacitor; Value: 0.01uF; U/M: EA; Cap_F: 0.00000001; Tolerance_%: 10; Value1: Unknown; VDC_V: 50; Value2: 50V; TaMin_C: -55; TaMax_C: 125; SizeArea_mm2: 1.28; SizeAreaWB_mm2: 4.68; SizeX_mm: 1.6; SizeY_mm: 0.8; SizeZ_mm: 1; AEC Category: Q200; AEC Qualified: Y
C351-C353 = 293D475X9025C2TE3: CAP, TA, 4.7 µF, 25 V, +/- 10%, 2 ohm, SMD; Manufacturer: Vishay-Sprague; Polarized: Y; CompType: Capacitor; Value: 4.7uF; U/M: EA; Cap_F: 0.0000047; Tolerance_%: 10; Value1: 2 ohm; VDC_V: 25; Value2: 25V; ESR_ohm: 2; IRMS_A: 0.24; TaMin_C: -55; TaMax_C: 125; Cap_Case: C; SizeAreaWB_mm2: 41.6; SizeArea_mm2: 19.2; SizeX_mm: 6; SizeY_mm: 3.2; SizeZ_mm: 2.8; AEC Category: Q200
Cff = C1608X7R2A223K080AA: CAP, CERM, 0.022 µF, 100 V, +/- 10%, X7R, 0603; Manufacturer: TDK; Polarized: N; CompType: Capacitor; Value: 0.022uF; U/M: EA; Cap_F: 0.000000022; Tolerance_%: 10; ESR_ohm: 0.037; Value1: 0.037 ohm; VDC_V: 100; Value2: 100V; TaMin_C: -55; TaMax_C: 125; SizeArea_mm2: 1.28; SizeAreaWB_mm2: 4.68; SizeX_mm: 1.6; SizeY_mm: 0.8; SizeZ_mm: 1; AEC Category: Q200
Cff2 Cff3 = 08055C223KAT2A: CAP, CERM, 0.022uF, 50V, +/-10%, X7R, 0805; Manufacturer: AVX; Polarized: N; CompType: Capacitor; U/M: EA; Cap_F: 0.000000022; Tolerance_%: 10; ESR_Ohm: 0.052; Value1: 0.052 ohm; VDC_V: 50; TaMin_C: -55; TaMax_C: 125; Cap_Case: 0805
Cout1 = C2012JB1V226M125AC: CAP, CERM, 22 µF, 35 V, +/- 20%, JB, 0805; Manufacturer: TDK; Polarized: N; CompType: Capacitor; Value: 22uF; U/M: EA; Cap_F: 0.000022; Tolerance_%: 20; Value1: Unknown; VDC_V: 35; Value2: 35V; TaMin_C: -25; TaMax_C: 85; Cap_Case: 0805; SizeArea_mm2: 2.5; SizeAreaWB_mm2: 6.75; SizeX_mm: 2; SizeY_mm: 1.25; SizeZ_mm: 1.45; AEC Category: Q200
Cout5 = C3225X6S0J107M250AC: CAP, CERM, 100 µF, 6.3 V, +/- 20%, X6S, 1210; Manufacturer: TDK; Polarized: N; CompType: Capacitor; Value: 100uF; U/M: EA; Cap_F: 0.0001; Tolerance_%: 20; ESR_ohm: 0.005496; Value1: 0.005496 ohm; VDC_V: 6.3; Value2: 6.3V; IRMS_A: 3.13651; TaMin_C: -55; TaMax_C: 105; SizeArea_mm2: 8; SizeAreaWB_mm2: 14.7; SizeX_mm: 3.2; SizeY_mm: 2.5; SizeZ_mm: 2.8; AEC Category: Q200
Cout6 = C0603C105K3RACTU: CAP, CERM, 1 µF, 25 V, +/- 10%, X7R, 0603; Manufacturer: Kemet; Polarized: N; CompType: Capacitor; Value: 1uF; U/M: EA; Cap_F: 0.000001; Tolerance_%: 10; Value1: Unknown; VDC_V: 25; Value2: 25V; TaMin_C: -55; TaMax_C: 125; SizeArea_mm2: 1.28; SizeAreaWB_mm2: 4.68; SizeX_mm: 1.6; SizeY_mm: 0.8; SizeZ_mm: 1; AEC Category: Q200
Css = CGA3E2X7R2A472K080AA: CAP, CERM, 4700 pF, 100 V, +/- 10%, X7R, AEC-Q200 Grade 1, 0603; Manufacturer: TDK; Polarized: N; CompType: Capacitor; Value: 4700pF; U/M: EA; Cap_F: 0.0000000047; Tolerance_%: 10; ESR_ohm: 0.469862; Value1: 0.469862 ohm; VDC_V: 100; Value2: 100V; IRMS_A: 0.32335; TaMin_C: -55; TaMax_C: 125; SizeArea_mm2: 1.28; SizeAreaWB_mm2: 4.68; SizeX_mm: 1.6; SizeY_mm: 0.8; SizeZ_mm: 1; AEC Category: Q200; AEC Qualified: Y
Css2 Css3 = GRM188R70J103KA01D: CAP, CERM, 0.01 µF, 6.3 V, +/- 10%, X7R, 0603; Manufacturer: MuRata; Polarized: N; CompType: Capacitor; Value: 0.01uF; U/M: EA; Cap_F: 0.00000001; Tolerance_%: 10; Value1: Unknown; VDC_V: 6.3; Value2: 6.3V; TaMin_C: -55; TaMax_C: 125; SizeArea_mm2: 1.28; SizeAreaWB_mm2: 4.68; SizeX_mm: 1.6; SizeY_mm: 0.8; SizeZ_mm: 1; AEC Category: Q200
D1 = MBRS4201T3G: Diode, Schottky, 200V, 4A, SMC; Manufacturer: ON Semiconductor; Io_A: 4
D5 = DFLS1100-7: Manufacturer Name: Diodes Inc.
D14 D18 D21 D22 = 150060RS75000: LED, Red, SMD; Manufacturer: Wurth Elektronik; Type: AlInGaP; Vf_V: 2; Value2: 2V; Io_A: 0.03; Vr_V: 5; Tjmax_C: 85; Power_TotalModule: 0.072; Value1: 0.072W; Angle: 140; U/M: EA
J8 = 691213710002: Terminal Block, 2x1, Brass, TH; Manufacturer: Wurth Elektronik; SymbolCreator: a0412235; Pitch_mm: 5; Gender: Female; Row_Count: 1
J34 = TMM-103-01-G-S-SM: Header, 2mm, 3x1, Gold, SMT; Manufacturer: Samtec; SymbolCreator: a0799628; Pitch_mm: 2; Gender: Male; Shrouded: N; Row_Count: 1; Current_A: 3.2; Voltage_V: 500; Cert_CSA: Y
L1 = DR73-331-R: Inductor, Shielded Drum Core, Ferrite, 330 µH, 0.42 A, 1.59 ohm, SMD; Manufacturer: Coiltronics; Value: 330uH; Ind_H: 330.0E-6; Imax_A: 0.42; Irms: 0.42A @ 40C rise; Isat: 0.44A @ 30% inductance drop; DCR_ohm: 1.59; Value2: 0.42A; AEC Category: Q200
L4 L5 L16-L19 = MPZ2012S601A: Ferrite Bead, 600 ohm @ 100MHz, 2A, 0805; Manufacturer: TDK; Imax_A: 2; DCR_ohm: 0.1; Value1: 0.1 ohm; ZTyp@100MHz_Ohm: 600
NT1 NT2 = Net-Tie: Single point connection between nets.; SymbolCreator: codlsc
R8-R15 R17-R20 R24-R27 R29-R36 = ERJ-2GE0R00X: RES, 0, 5%, 0.063 W, 0402; Manufacturer: Panasonic; CompType: Resistor; Value: 0; Value_Code: 0000; Tolerance_%: 5; Power_W: 0.063; Value2: 0.063W; VDC_V: 50; TempCo: 600 ppm/C; EIA_Code: E24; U/M: EA; AEC Category: Q200
R21 = CRCW06030000Z0EA: RES, 0, 5%, 0.1 W, 0603; Manufacturer: Vishay-Dale; CompType: Resistor; Value: 0; Value_Code: 0000; Tolerance_%: 5; Power_W: 0.1; Value2: 0.1W; VDC_V: 75; TempCo: 200 ppm/C; SizeArea_mm2: 1.28; SizeX_mm: 1.6; SizeY_mm: 0.8; SizeZ_mm: 1; EIA_Code: E24; U/M: EA; AEC Category: Q200
R22 = RT0603DRE074R7L: RES, 4.70, 0.5%, 0.1 W, 0603; Manufacturer: Yageo America; CompType: Resistor; Value: 4.70; Res_ohm: 4.7; Value_Code: 4R70; Tolerance_%: 0.5; Power_W: 0.1; Value2: 0.1W; VDC_V: 75; TempCo: 50 ppm/C; SizeArea_mm2: 1.28; SizeX_mm: 1.6; SizeY_mm: 0.8; SizeZ_mm: 1; EIA_Code: E192; U/M: EA; AEC Category: Q200
R40 = RT0603BRD07215KL: RES, 215 k, 0.1%, 0.1 W, 0603; Manufacturer: Yageo America; CompType: Resistor; Value: 215k; Res_ohm: 215000; Tolerance_%: 0.1; Value2: 0.1W; VDC_V: 75; TempCo: 25 ppm/C; SizeArea_mm2: 1.28; SizeX_mm: 1.6; SizeY_mm: 0.8; SizeZ_mm: 1; EIA_Code: E192; U/M: EA; AEC Category: Q200
R41 = RG1608P-2322-B-T5: RES, 23.2 k, 0.1%, 0.1 W, 0603; Manufacturer: Susumu Co Ltd; CompType: Resistor; Value: 23.2k; Res_ohm: 23200; Value_Code: 23k2; Tolerance_%: 0.1; Value2: 0.1W; VDC_V: 75; TempCo: 25 ppm/C; SizeArea_mm2: 1.28; SizeX_mm: 1.6; SizeY_mm: 0.8; SizeZ_mm: 1; EIA_Code: E192; U/M: EA; AEC Category: Q200
R42 = RG1608P-1651-B-T5: RES, 1.65 k, 0.1%, 0.1 W, 0603; Manufacturer: Susumu Co Ltd; CompType: Resistor; Value: 1.65k; Res_ohm: 1650; Value_Code: 1k65; Tolerance_%: 0.1; Value2: 0.1W; VDC_V: 75; TempCo: 25 ppm/C; SizeArea_mm2: 1.28; SizeX_mm: 1.6; SizeY_mm: 0.8; SizeZ_mm: 1; EIA_Code: E192; U/M: EA; AEC Category: Q200
R43 = RG1608P-3092-B-T5: RES, 30.9 k, 0.1%, 0.1 W, 0603; Manufacturer: Susumu Co Ltd; CompType: Resistor; Value: 30.9k; Res_ohm: 30900; Value_Code: 30k9; Tolerance_%: 0.1; Value2: 0.1W; VDC_V: 75; TempCo: 25 ppm/C; SizeArea_mm2: 1.28; SizeX_mm: 1.6; SizeY_mm: 0.8; SizeZ_mm: 1; EIA_Code: E192; U/M: EA; AEC Category: Q200
R44 = RT0603BRD072K15L: RES, 2.15 k, 0.1%, 0.1 W, 0603; Manufacturer: Yageo America; CompType: Resistor; Value: 2.15k; Res_ohm: 2150; Value_Code: 2k15; Tolerance_%: 0.1; Value2: 0.1W; VDC_V: 75; TempCo: 25 ppm/C; SizeArea_mm2: 1.28; SizeX_mm: 1.6; SizeY_mm: 0.8; SizeZ_mm: 1; EIA_Code: E192; U/M: EA; AEC Category: Q200
R45 = RT0603BRD0752K3L: RES, 52.3 k, 0.1%, 0.1 W, 0603; Manufacturer: Yageo America; CompType: Resistor; Value: 52.3k; Res_ohm: 52300; Value_Code: 52k3; Tolerance_%: 0.1; Value2: 0.1W; VDC_V: 75; TempCo: 25 ppm/C; SizeArea_mm2: 1.28; SizeX_mm: 1.6; SizeY_mm: 0.8; SizeZ_mm: 1; EIA_Code: E192; U/M: EA; AEC Category: Q200
R46 = RC0603JR-07330RL: RES, 330, 5%, 0.1 W, 0603; Manufacturer: Yageo America; CompType: Resistor; Value: 330; Value_Code: 330R; Tolerance_%: 5; Power_W: 0.1; Value2: 0.1W; VDC_V: 50; TempCo: 100 ppm/C; EIA_Code: E24; U/M: EA; AEC Category: Q200
R47 = RT0603BRD0718KL: RES, 18.0 k, 0.1%, 0.1 W, 0603; Manufacturer: Yageo America; CompType: Resistor; Value: 18.0k; Res_ohm: 18000; Value_Code: 18k0; Tolerance_%: 0.1; Value2: 0.1W; VDC_V: 75; TempCo: 25 ppm/C; SizeArea_mm2: 1.28; SizeX_mm: 1.6; SizeY_mm: 0.8; SizeZ_mm: 1; EIA_Code: E192; U/M: EA; AEC Category: Q200
R50 = RG1608P-203-B-T5: RES, 20.0 k, 0.1%, 0.1 W, 0603; Manufacturer: Susumu Co Ltd; CompType: Resistor; Value: 20.0k; Res_ohm: 20000; Value_Code: 20k0; Tolerance_%: 0.1; Value2: 0.1W; VDC_V: 75; TempCo: 25 ppm/C; SizeArea_mm2: 1.28; SizeX_mm: 1.6; SizeY_mm: 0.8; SizeZ_mm: 1; EIA_Code: E192; U/M: EA; AEC Category: Q200
R246 R247 = RG1608P-4992-B-T5: RES, 49.9 k, 0.1%, 0.1 W, 0603; Manufacturer: Susumu Co Ltd; CompType: Resistor; Value: 49.9k; Res_ohm: 49900; Value_Code: 49k9; Tolerance_%: 0.1; Value2: 0.1W; VDC_V: 75; TempCo: 25 ppm/C; SizeArea_mm2: 1.28; SizeX_mm: 1.6; SizeY_mm: 0.8; SizeZ_mm: 1; EIA_Code: E192; U/M: EA; AEC Category: Q200
Renb = CRCW080520K5FKEA: RES, 20.5 k, 1%, 0.125 W, 0805; Manufacturer: Vishay-Dale; CompType: Resistor; Value: 20.5k; Res_ohm: 20500; Value_Code: 20k5; Tolerance_%: 1; Power_W: 0.125; Value2: 0.125W; VDC_V: 150; TempCo: 100 ppm/C; EIA_Code: E96; U/M: EA; AEC Category: Q200
Renb2 Renb3 = RG1608P-3571-B-T5: RES, 3.57 k, 0.1%, 0.1 W, 0603; Manufacturer: Susumu Co Ltd; CompType: Resistor; Value: 3.57k; Res_ohm: 3570; Value_Code: 3k57; Tolerance_%: 0.1; Value2: 0.1W; VDC_V: 75; TempCo: 25 ppm/C; SizeArea_mm2: 1.28; SizeX_mm: 1.6; SizeY_mm: 0.8; SizeZ_mm: 1; EIA_Code: E192; U/M: EA; AEC Category: Q200
Rent = RT0805BRD07118KL: RES, 118k ohm, 0.1%, 0.125W, 0805; Manufacturer: Yageo America; CompType: Resistor; Res_ohm: 118000; Tolerance_%: 0.1; Power_W: 0.125; VDC_V: 150; TempCo: 25 ppm/C; EIA_Code: E192; U/M: EA
Rent2 Rent3 = RT0603BRD0768K1L: RES, 68.1 k, 0.1%, 0.1 W, 0603; Manufacturer: Yageo America; CompType: Resistor; Value: 68.1k; Res_ohm: 68100; Value_Code: 68k1; Tolerance_%: 0.1; Value2: 0.1W; VDC_V: 75; TempCo: 25 ppm/C; SizeArea_mm2: 1.28; SizeX_mm: 1.6; SizeY_mm: 0.8; SizeZ_mm: 1; EIA_Code: E192; U/M: EA; AEC Category: Q200
Rfbb = RG1608P-152-B-T5: RES, 1.50 k, 0.1%, 0.1 W, 0603; Manufacturer: Susumu Co Ltd; CompType: Resistor; Value: 1.50k; Res_ohm: 1500; Value_Code: 1k50; Tolerance_%: 0.1; Value2: 0.1W; VDC_V: 75; TempCo: 25 ppm/C; SizeArea_mm2: 1.28; SizeX_mm: 1.6; SizeY_mm: 0.8; SizeZ_mm: 1; EIA_Code: E192; U/M: EA; AEC Category: Q200
Rfbb3 Rfbb5 = RT0805BRD071K07L: RES, 1.07 k, 0.1%, 0.125 W, 0805; Manufacturer: Yageo America; CompType: Resistor; Value: 1.07k; Res_ohm: 1070; Value_Code: 1k07; Tolerance_%: 0.1; Power_W: 0.125; Value2: 0.125W; VDC_V: 150; TempCo: 25 ppm/C; EIA_Code: E192; U/M: EA; AEC Category: Q200
Rfbt = RT0603BRD0734KL: RES, 34.0 k, 0.1%, 0.1 W, 0603; Manufacturer: Yageo America; CompType: Resistor; Value: 34.0k; Res_ohm: 34000; Value_Code: 34k0; Tolerance_%: 0.1; Value2: 0.1W; VDC_V: 75; TempCo: 25 ppm/C; SizeArea_mm2: 1.28; SizeX_mm: 1.6; SizeY_mm: 0.8; SizeZ_mm: 1; EIA_Code: E192; U/M: EA; AEC Category: Q200
Rfbt2 = CPF0603B6K34E: RES, 6.34 k, 0.1%, 0.063 W, 0603; Manufacturer: TE Connectivity; CompType: Resistor; Value: 6.34k; Res_ohm: 6340; Value_Code: 6k34; Tolerance_%: 0.1; Power_W: 0.063; Value2: 0.063W; VDC_V: 50; TempCo: 25 ppm/C; SizeArea_mm2: 1.28; SizeX_mm: 1.6; SizeY_mm: 0.8; SizeZ_mm: 1; EIA_Code: E192; U/M: EA; AEC Category: Q200
Rfbt3 = RG1608P-4021-B-T5: RES, 4.02 k, 0.1%, 0.1 W, 0603; Manufacturer: Susumu Co Ltd; CompType: Resistor; Value: 4.02k; Res_ohm: 4020; Value_Code: 4k02; Tolerance_%: 0.1; Value2: 0.1W; VDC_V: 75; TempCo: 25 ppm/C; SizeArea_mm2: 1.28; SizeX_mm: 1.6; SizeY_mm: 0.8; SizeZ_mm: 1; EIA_Code: E192; U/M: EA; AEC Category: Q200
Ron = RT0603BRD07383KL: RES, 383 k, 0.1%, 0.1 W, 0603; Manufacturer: Yageo America; CompType: Resistor; Value: 383k; Res_ohm: 383000; Tolerance_%: 0.1; Value2: 0.1W; VDC_V: 75; TempCo: 25 ppm/C; SizeArea_mm2: 1.28; SizeX_mm: 1.6; SizeY_mm: 0.8; SizeZ_mm: 1; EIA_Code: E192; U/M: EA; AEC Category: Q200
Ron2 = RT0603BRD07113KL: RES, 113 k, 0.1%, 0.1 W, 0603; Manufacturer: Yageo America; CompType: Resistor; Value: 113k; Res_ohm: 113000; Tolerance_%: 0.1; Value2: 0.1W; VDC_V: 75; TempCo: 25 ppm/C; SizeArea_mm2: 1.28; SizeX_mm: 1.6; SizeY_mm: 0.8; SizeZ_mm: 1; EIA_Code: E192; U/M: EA; AEC Category: Q200
Ron3 = RT0603BRD0778K7L: RES, 78.7 k, 0.1%, 0.1 W, 0603; Manufacturer: Yageo America; CompType: Resistor; Value: 78.7k; Res_ohm: 78700; Value_Code: 78k7; Tolerance_%: 0.1; Value2: 0.1W; VDC_V: 75; TempCo: 25 ppm/C; SizeArea_mm2: 1.28; SizeX_mm: 1.6; SizeY_mm: 0.8; SizeZ_mm: 1; EIA_Code: E192; U/M: EA; AEC Category: Q200
U5 = LMZ14202TZX-ADJ/NOPB: 2A SIMPLE SWITCHER® Power Module with 42V Maximum Input, 7 pin TO-PMOD; Manufacturer: Texas Instruments; PackageTopMarking: NSUZXYTTE#*LMZ14202*TZ-ADJ; PowerWise: Y
U6-U8 = TPS7A4700RGWR: 36-V, 1-A, 4.17-μVRMS, RF LDO Voltage Regulator, RGW0020A; Alternate PartNumber: TPS7A4700RGWT; Manufacturer: Texas Instruments; SymbolCreator: a0412235; CompType: IC; U/M: EA
U9 = LM5574MT: SIMPLE SWITCHER® 75V, 0.5A Step-Down Switching Regulator, 16-pin TSSOP; Manufacturer: Texas Instruments; PackageTopMarking: NSUZXYTT*LM5574*MT; PowerWise: Y
U10 = LM7705MM/NOPB: Low Noise Negative Bias Generator, 8-pin Mini SOIC, Pb-Free; Manufacturer: Texas Instruments; PackageTopMarking: ZXTT*F26A; PowerWise: N; CompType: OtherParts
U11 = TPS7A3001MDGNTEP: Single Output High PSRR LDO, 200 mA, Adjustable -1.18 to -33 V Output, -3 to -36 V Input, with Ultra-Low Noise, 8-pin MSOP (DGN), -55 to 125 degC, Green (RoHS & no Sb/Br); Manufacturer: Texas Instruments; Alternate PartNumber: Equivalent; Accuracy(%): 1.5; Iout(Max)(A): 0.2; Iq(Typ)(mA): 0.05; SubFamily: Single Channel LDO; Vdo(Typ)(mV): 216
U22 = LMZ14201TZX-ADJ/NOPB: 1A SIMPLE SWITCHER® Power Module with 42V Maximum Input, 7 pin TO-PMOD; Manufacturer: Texas Instruments; PackageTopMarking: NSUZXYTTE#*LMZ14201*TZ-ADJ; PowerWise: Y
U23 = LMZ14203TZ-ADJ/NOPB: 3A SIMPLE SWITCHER® Power Module with 42V Maximum Input Voltage, 7-pin TO-PMOD, Pb-Free; Manufacturer: Texas Instruments; PackageTopMarking: NSUZXYTTE#*LMZ14203*TZ-ADJ; PowerWise: Y

## Sheet OPA625 ADC Driver_Connectors.SchDoc
size 431 x 279 mm; Date: Not shown in title block; ApprovedBy: Not shown in title block; CheckedBy: Not shown in title block; Author: Not shown in title block; CompanyName: Not shown in title block; Engineer: Not shown in title block; Organization: Not shown in title block; Address1: Not shown in title block; Address2: Not shown in title block; Address3: Not shown in title block; Address4: Not shown in title block; DocumentNumber: 3; Revision: Use project parameter SCH_Rev; SheetNumber: 3; SheetTotal: 8; PageSetup: Record=PageOptions¦CenterHorizontal=True¦CenterVertical=True¦PrintScale=1.00¦XCorrection=1.00¦YCorrection=1.00¦PrintKind=0¦BorderSize=5000000¦LeftOffset=0¦BottomOffset=0¦Orientation=2¦PaperLength=1000¦PaperWidth=1000¦Scale=100¦PaperSource=15¦PrintQuality=600¦MediaType=1¦DitherType=10¦PaperKind=Letter¦PrintScaleMode=1
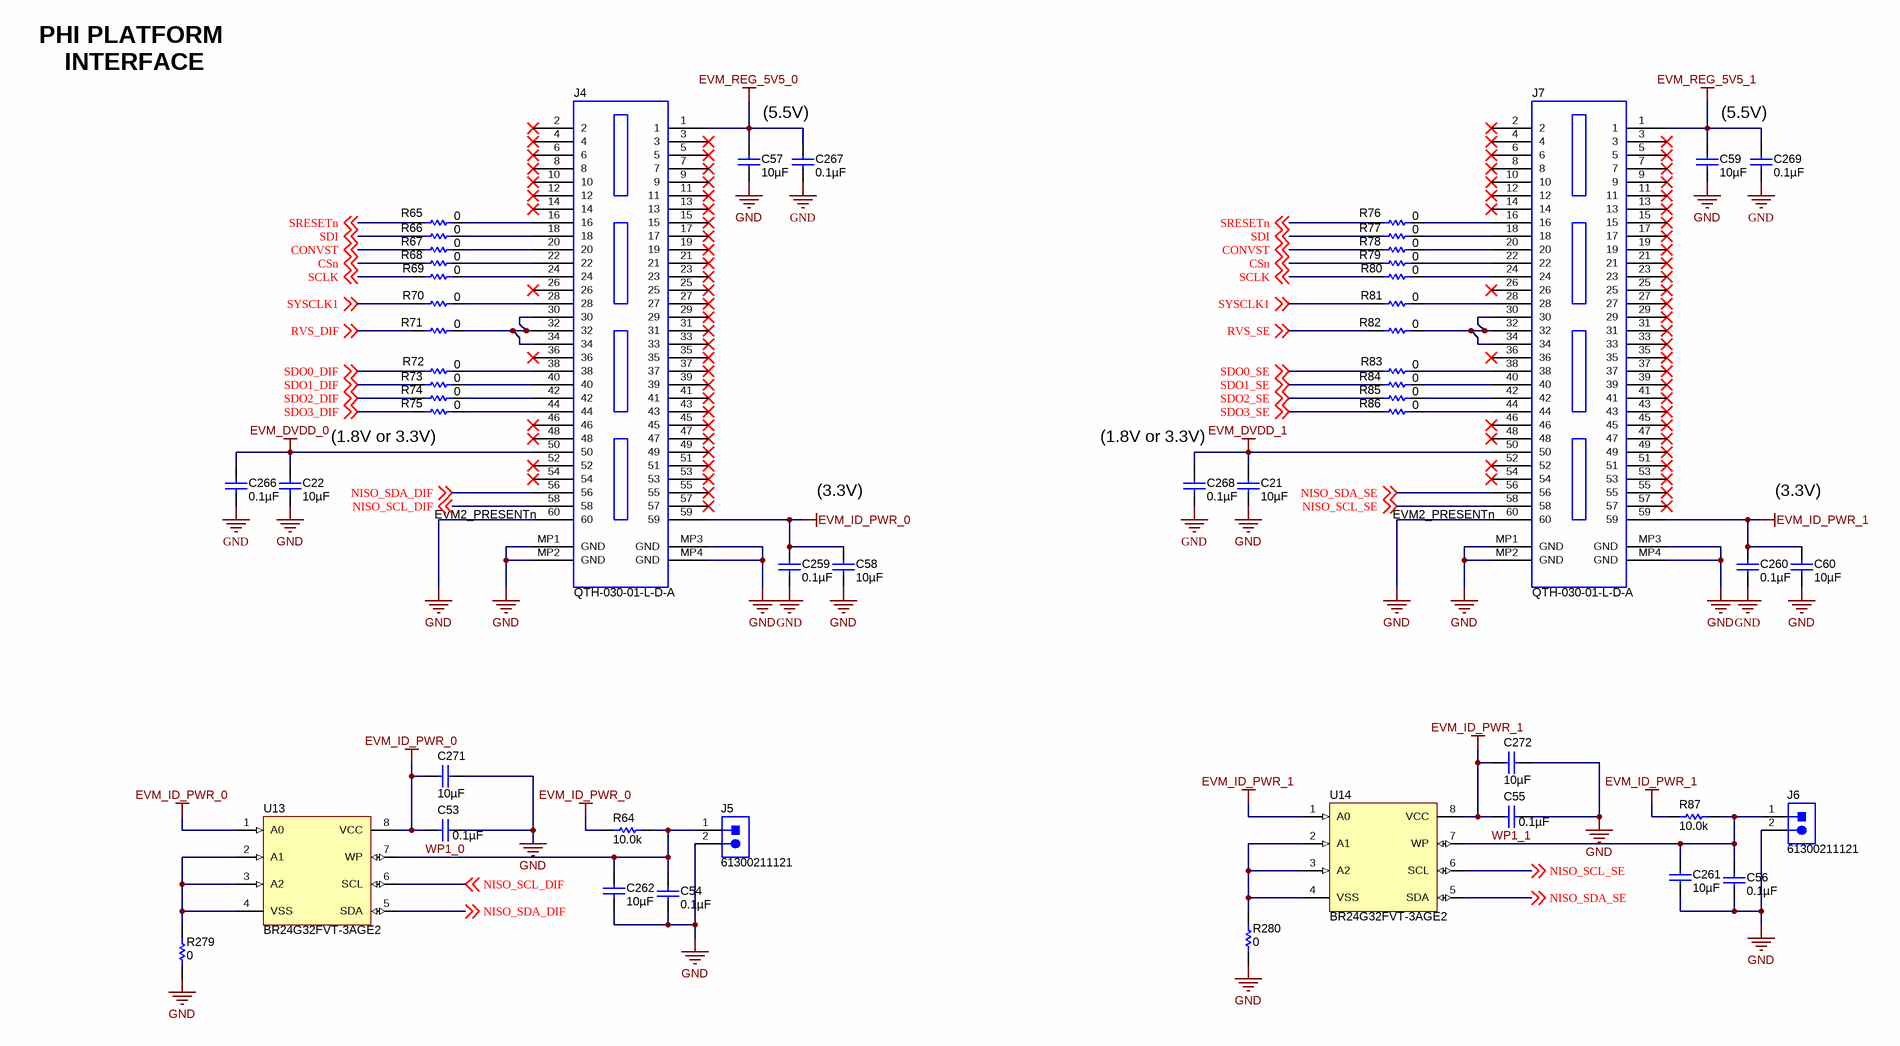
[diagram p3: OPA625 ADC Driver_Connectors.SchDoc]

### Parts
C21  ValueDisplayed: 10µF  [0805_HV]  (hidden comment: GRM21BR71A106KE51L)
C22  ValueDisplayed: 10µF  [0805_HV]  (hidden comment: GRM21BR71A106KE51L)
C53  ValueDisplayed: 0.1µF  [0402]  (hidden comment: GRM155R71C104KA88D)
C54  ValueDisplayed: 0.1µF  [0402]  (hidden comment: GRM155R71C104KA88D)
C55  ValueDisplayed: 0.1µF  [0402]  (hidden comment: GRM155R71C104KA88D)
C56  ValueDisplayed: 0.1µF  [0402]  (hidden comment: GRM155R71C104KA88D)
C57  ValueDisplayed: 10µF  [0805_HV]  (hidden comment: GRM21BR71A106KE51L)
C58  ValueDisplayed: 10µF  [0805_HV]  (hidden comment: GRM21BR71A106KE51L)
C59  ValueDisplayed: 10µF  [0805_HV]  (hidden comment: GRM21BR71A106KE51L)
C60  ValueDisplayed: 10µF  [0805_HV]  (hidden comment: GRM21BR71A106KE51L)
C259  ValueDisplayed: 0.1µF  [0603]  (hidden comment: C0603C104J3RACTU)
C260  ValueDisplayed: 0.1µF  [0603]  (hidden comment: C0603C104J3RACTU)
C261  ValueDisplayed: 10µF  [0805_HV]  (hidden comment: GRM21BR71A106KE51L)
C262  ValueDisplayed: 10µF  [0805_HV]  (hidden comment: GRM21BR71A106KE51L)
C266  ValueDisplayed: 0.1µF  [0603]  (hidden comment: C0603C104J3RACTU)
C267  ValueDisplayed: 0.1µF  [0603]  (hidden comment: C0603C104J3RACTU)
C268  ValueDisplayed: 0.1µF  [0603]  (hidden comment: C0603C104J3RACTU)
C269  ValueDisplayed: 0.1µF  [0603]  (hidden comment: C0603C104J3RACTU)
C271  ValueDisplayed: 10µF  [0805_HV]  (hidden comment: GRM21BR71A106KE51L)
C272  ValueDisplayed: 10µF  [0805_HV]  (hidden comment: GRM21BR71A106KE51L)
J4  QTH-030-01-L-D-A  [Samtec_QTH-030-01-x-D-A]
J5  61300211121  [WURTH_61300211121]
J6  61300211121  [WURTH_61300211121]
J7  QTH-030-01-L-D-A  [Samtec_QTH-030-01-x-D-A]
R64  ValueDisplayed: 10.0k  [0603]  (hidden comment: CRCW060310K0FKEA)
R65  ValueDisplayed: 0  [0402]  (hidden comment: ERJ-2GE0R00X)
R66  ValueDisplayed: 0  [0402]  (hidden comment: ERJ-2GE0R00X)
R67  ValueDisplayed: 0  [0402]  (hidden comment: ERJ-2GE0R00X)
R68  ValueDisplayed: 0  [0402]  (hidden comment: ERJ-2GE0R00X)
R69  ValueDisplayed: 0  [0402]  (hidden comment: ERJ-2GE0R00X)
R70  ValueDisplayed: 0  [0402]  (hidden comment: ERJ-2GE0R00X)
R71  ValueDisplayed: 0  [0402]  (hidden comment: ERJ-2GE0R00X)
R72  ValueDisplayed: 0  [0402]  (hidden comment: ERJ-2GE0R00X)
R73  ValueDisplayed: 0  [0402]  (hidden comment: ERJ-2GE0R00X)
R74  ValueDisplayed: 0  [0402]  (hidden comment: ERJ-2GE0R00X)
R75  ValueDisplayed: 0  [0402]  (hidden comment: ERJ-2GE0R00X)
R76  ValueDisplayed: 0  [0402]  (hidden comment: ERJ-2GE0R00X)
R77  ValueDisplayed: 0  [0402]  (hidden comment: ERJ-2GE0R00X)
R78  ValueDisplayed: 0  [0402]  (hidden comment: ERJ-2GE0R00X)
R79  ValueDisplayed: 0  [0402]  (hidden comment: ERJ-2GE0R00X)
R80  ValueDisplayed: 0  [0402]  (hidden comment: ERJ-2GE0R00X)
R81  ValueDisplayed: 0  [0402]  (hidden comment: ERJ-2GE0R00X)
R82  ValueDisplayed: 0  [0402]  (hidden comment: ERJ-2GE0R00X)
R83  ValueDisplayed: 0  [0402]  (hidden comment: ERJ-2GE0R00X)
R84  ValueDisplayed: 0  [0402]  (hidden comment: ERJ-2GE0R00X)
R85  ValueDisplayed: 0  [0402]  (hidden comment: ERJ-2GE0R00X)
R86  ValueDisplayed: 0  [0402]  (hidden comment: ERJ-2GE0R00X)
R87  ValueDisplayed: 10.0k  [0603]  (hidden comment: CRCW060310K0FKEA)
R279  ValueDisplayed: 0  [0402]  (hidden comment: ERJ-2GE0R00X)
R280  ValueDisplayed: 0  [0402]  (hidden comment: ERJ-2GE0R00X)
U13  BR24G32FVT-3AGE2  [TSOP65P640X120-8N]
U14  BR24G32FVT-3AGE2  [TSOP65P640X120-8N]

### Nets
EVM_DVDD_0: C22.1 C266.1 J4.50
EVM_DVDD_1: C21.1 C268.1 J7.50
EVM_ID_PWR_0: C53.2 C58.1 C259.1 C271.1 J4.59 R64.2 U13.1(A0) U13.8(VCC)
EVM_ID_PWR_1: C55.2 C60.1 C260.1 C272.1 J7.59 R87.2 U14.1(A0) U14.8(VCC)
EVM_REG_5V5_0: C57.1 C267.1 J4.1
EVM_REG_5V5_1: C59.1 C269.1 J7.1
GND: C21.2 C22.2 C53.1 C54.1 C55.1 C56.1 C57.2 C58.2 C59.2 C60.2 C259.2 C260.2 C261.2 C262.2 C266.2 C267.2 C268.2 C269.2 C271.2 C272.2 J4.60 J4.MP1(GND) J4.MP2(GND) J4.MP3(GND) J4.MP4(GND) J5.2 J6.2 J7.60 J7.MP1(GND) J7.MP2(GND) J7.MP3(GND) J7.MP4(GND) R279.1 R280.1
CONVST: R67.1 R78.1 ; off-sheet CONVST
CSn: R68.1 R79.1 ; off-sheet CSn
NISO_SCL_DIF: J4.58 U13.6(SCL) ; off-sheet NISO_SCL_DIF
NISO_SCL_SE: J7.58 U14.6(SCL) ; off-sheet NISO_SCL_SE
NISO_SDA_DIF: J4.56 U13.5(SDA) ; off-sheet NISO_SDA_DIF
NISO_SDA_SE: J7.56 U14.5(SDA) ; off-sheet NISO_SDA_SE
RVS_DIF: R71.1 ; off-sheet RVS_DIF
RVS_SE: R82.1 ; off-sheet RVS_SE
SCLK: R69.1 R80.1 ; off-sheet SCLK
SDI: R66.1 R77.1 ; off-sheet SDI
SDO0_DIF: R72.1 ; off-sheet SDO0_DIF
SDO0_SE: R83.1 ; off-sheet SDO0_SE
SDO1_DIF: R73.1 ; off-sheet SDO1_DIF
SDO1_SE: R84.1 ; off-sheet SDO1_SE
SDO2_DIF: R74.1 ; off-sheet SDO2_DIF
SDO2_SE: R85.1 ; off-sheet SDO2_SE
SDO3_DIF: R75.1 ; off-sheet SDO3_DIF
SDO3_SE: R86.1 ; off-sheet SDO3_SE
SRESETn: R65.1 R76.1 ; off-sheet SRESETn
SYSCLK1: R70.1 R81.1 ; off-sheet SYSCLK1
WP1_0: C54.2 C262.1 J5.1 R64.1 U13.7(WP)
WP1_1: C56.2 C261.1 J6.1 R87.1 U14.7(WP)
NetJ4_16: J4.16 R65.2
NetJ4_18: J4.18 R66.2
NetJ4_20: J4.20 R67.2
NetJ4_22: J4.22 R68.2
NetJ4_24: J4.24 R69.2
NetJ4_28: J4.28 R70.2
NetJ4_30: J4.30 J4.32 J4.34 R71.2
NetJ4_38: J4.38 R72.2
NetJ4_40: J4.40 R73.2
NetJ4_42: J4.42 R74.2
NetJ4_44: J4.44 R75.2
NetJ7_16: J7.16 R76.2
NetJ7_18: J7.18 R77.2
NetJ7_20: J7.20 R78.2
NetJ7_22: J7.22 R79.2
NetJ7_24: J7.24 R80.2
NetJ7_28: J7.28 R81.2
NetJ7_30: J7.30 J7.32 J7.34 R82.2
NetJ7_38: J7.38 R83.2
NetJ7_40: J7.40 R84.2
NetJ7_42: J7.42 R85.2
NetJ7_44: J7.44 R86.2
NetR279_2: R279.2 U13.2(A1) U13.3(A2) U13.4(VSS)
NetR280_2: R280.2 U14.2(A1) U14.3(A2) U14.4(VSS)

Not connected (* = marked no-connect by the designer): J4 2* 3* 4* 5* 6* 7* 8* 9* 10* 11* 12* 13* 14* 15* 17* 19* 21* 23* 25* 26* 27* 29* 31* 33* 35* 36* 37* 39* 41* 43* 45* 46* 47* 48* 49* 51* 52* 53* 54* 55* 57*; J7 2* 3* 4* 5* 6* 7* 8* 9* 10* 11* 12* 13* 14* 15* 17* 19* 21* 23* 25* 26* 27* 29* 31* 33* 35* 36* 37* 39* 41* 43* 45* 46* 47* 48* 49* 51* 52* 53* 54* 55* 57*

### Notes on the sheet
- PHI PLATFORM
  INTERFACE
- (5.5V)
- (near R75) (1.8V or 3.3V)
- (near C268) (1.8V or 3.3V)
- (near J4) EVM2_PRESENTn
- (3.3V)
- (near J7) EVM2_PRESENTn

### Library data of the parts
C21 C22 C57-C60 C261 C262 C271 C272 = GRM21BR71A106KE51L: CAP, CERM, 10 µF, 10 V, +/- 10%, X7R, 0805; Manufacturer: MuRata; Polarized: N; CompType: Capacitor; Value: 10uF; U/M: EA; Cap_F: 0.00001; Tolerance_%: 10; ESR_ohm: 0.003; Value1: 0.003 ohm; Value2: 10V; TaMin_C: -55; TaMax_C: 125; Cap_Case: 0805; AEC Category: Q200
C53-C56 = GRM155R71C104KA88D: CAP, CERM, 0.1 µF, 16 V, +/- 10%, X7R, 0402; Manufacturer: MuRata; Polarized: N; CompType: Capacitor; Value: 0.1uF; U/M: EA; Cap_F: 0.0000001; Tolerance_%: 10; Value1: Unknown; VDC_V: 16; Value2: 16V; TaMin_C: -55; TaMax_C: 125
C259 C260 C266-C269 = C0603C104J3RACTU: CAP, CERM, 0.1 µF, 25 V, +/- 5%, X7R, 0603; Manufacturer: Kemet; Polarized: N; CompType: Capacitor; Value: 0.1uF; U/M: EA; Cap_F: 0.0000001; Tolerance_%: 5; Value1: Unknown; VDC_V: 25; Value2: 25V; TaMin_C: -55; TaMax_C: 125
J4 J7 = QTH-030-01-L-D-A: Header(Shrouded), 19.7mil, 30x2, Gold, SMT; Manufacturer: Samtec; SymbolCreator: Altium; Pitch_mm: 0.5; Gender: Male; Shrouded: Y; Row_Count: 2
J5 J6 = 61300211121: Header, 2.54 mm, 2x1, Gold, TH; Manufacturer: Wurth Elektronik eiSos; SymbolCreator: a0412235; U/M: EA
R64 R87 = CRCW060310K0FKEA: RES, 10.0 k, 1%, 0.1 W, 0603; Manufacturer: Vishay-Dale; CompType: Resistor; Value: 10.0k; Res_ohm: 10000; Value_Code: 10k0; Tolerance_%: 1; Power_W: 0.1; Value2: 0.1W; VDC_V: 75; TempCo: 100 ppm/C; EIA_Code: E96; U/M: EA
R65-R86 R279 R280 = ERJ-2GE0R00X: as R8 on sheet OPA625 ADC Driver_Power
U13 U14 = BR24G32FVT-3AGE2: I2C BUS EEPROM (2-Wire), TSSOP-B8; Manufacturer: Rohm; SymbolCreator: a0411947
